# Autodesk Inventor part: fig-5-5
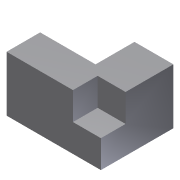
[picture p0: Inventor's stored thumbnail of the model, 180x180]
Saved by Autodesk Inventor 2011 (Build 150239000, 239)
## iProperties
Created: 2010-02
Part Number: fig-5-5
Document SubType Name: Modeling
Designer: CADSoft
Density: 1 g/cm^3
Author: CADSoft
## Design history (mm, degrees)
sketch "Sketch1"
  geometry: L1 (0, 26.227)-(0, 12.145); L2 (0, 12.145)-(-20.026, 12.145); L3 (-20.026, 12.145)-(-20.026, 0); L4 (-20.026, 0)-(14.083, 0); L5 (14.083, 0)-(14.083, 26.227); L6 (14.083, 26.227)-(0, 26.227); 1 further point
  constraints: 12 end point
extrude "Extrusion1" new body sketch "Sketch1" distance "d0" = 20; taper "d1" = 0 deg
sketch "Sketch2"
  geometry: L1 (14.083, 0)-(3.983, 0); L2 (3.983, 0)-(3.983, 8.922); L3 (3.983, 8.922)-(14.083, 8.922); L4 (14.083, 8.922)-(14.083, 0); 1 further point
  constraints: 8 end point
extrude "Extrusion2" cut sketch "Sketch2" distance "d2" = 10; taper "d3" = 0 deg
body "Solid1"
